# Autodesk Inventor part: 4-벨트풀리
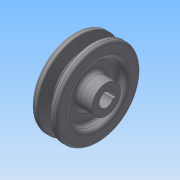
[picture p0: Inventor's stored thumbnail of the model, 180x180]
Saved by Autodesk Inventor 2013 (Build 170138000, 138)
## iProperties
Created: 2015-02
Part Number: 4-벨트풀리
Material: 일반
Document SubType Name: Modeling
Designer: Administrator
Density: 1 g/cm^3
Author: Administrator
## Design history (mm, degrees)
sketch "스케치1"
  geometry: L1 (0, 0)-(25, 0); L2 (0, 0)-(0, 11); L3 (0, 11)-(6, 11); L4 (6, 11)-(6, 21.5); L5 (6, 21.5)-(0, 21.5); L6 (0, 21.5)-(0, 32.5); L7 (0, 32.5)-(4.675, 32.5); L8 (4.675, 32.5)-(7.426, 23.5); L9 (7.426, 23.5)-(11.574, 23.5); L10 (11.574, 23.5)-(14.325, 32.5); L11 (14.325, 32.5)-(19, 32.5); L12 (19, 32.5)-(19, 21.5); L13 (19, 21.5)-(13, 21.5); L14 (13, 21.5)-(13, 11); L15 (13, 11)-(25, 11); L16 (25, 11)-(25, 0); 2 further points
  constraints: 32 end point, 6 parallel, 6 perpendicular, 5 collinear, 3 equal length, 2 point on line, 1 horizontal, 1 horizontal alignment
  dimensions: "d0" = 25 distance of L1.start L1.end; "d1" = 43 diameter of L5 L1; "d2" = 22 diameter of L3 L1; "d3" = 6 distance of L4.end L5.end; "d4" = 19 distance between parallel lines of L6 L12; "d5" = 65 diameter of L7 L1; "d6" = 8 distance of point (13.5, 29.8) point (5.5, 29.8); "d7" = 34 deg angle of L10 L8; "d8" = 2.7 distance from line of L11 point (13.5, 29.8); "d9" = 6.3 distance from line of point (13.5, 29.8) L9
revolve "회전1" sketch "스케치1" stored, may be unused: angle "d10" = 90 deg
fillet "모깎기1" dims "d11" = 3, "d12" = 2, "d13" = 1, "d14" = 0.5
sketch "스케치2"
  geometry: L1 (-2, 5.123)-(-2, 7.3); L2 (-2, 7.3)-(2, 7.3); L3 (2, 7.3)-(2, 5.123); C1 r 11 at (0, 0) reference; A1 r 5.5 centre (0, 0) between (-2, 5.123) and (2, 5.123); 1 further point
  constraints: 6 end point, 2 point on circle, 1 centre point, 1 coincident, 1 midpoint, 1 parallel, 1 perpendicular, 1 vertical, 1 vertical alignment
  dimensions: "d15" = 11 diameter of A1; "d17" = 4 distance of L1.end L2.end; "d18" = 12.8 dimension on A1 L2
extrude "돌출1" cut sketch "스케치2" stored distance "d19" = 10; taper "d20" = 0 deg
node "솔리드1"
